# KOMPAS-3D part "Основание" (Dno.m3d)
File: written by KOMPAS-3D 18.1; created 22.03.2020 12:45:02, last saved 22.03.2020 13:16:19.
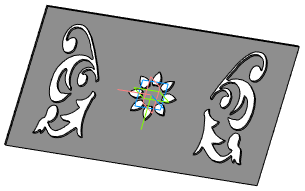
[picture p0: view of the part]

Document properties: Автор: windwican@hotmail.com; Полное имя файла: C:\Users\windw\Desktop\shkatilka1\bez petli\Dno.m3d

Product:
- Part/product: Основание
    Масса: 4.38205

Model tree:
1. Эскиз:1
2. Элемент выдавливания:2
     Расстояние 1 = 5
